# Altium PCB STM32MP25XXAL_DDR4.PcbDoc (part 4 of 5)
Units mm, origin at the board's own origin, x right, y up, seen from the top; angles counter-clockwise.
Board outline 125 x 95 mm, 6 copper layers (Top Layer, Signal Layer 1, Signal Layer 2, Signal Layer 3, Signal Layer 4, Bottom Layer), stack 1.403 mm thick; 220 components, 316 nets, 1103 pads, 939 vias.
Unrouted connection lines stored in the file: 5.
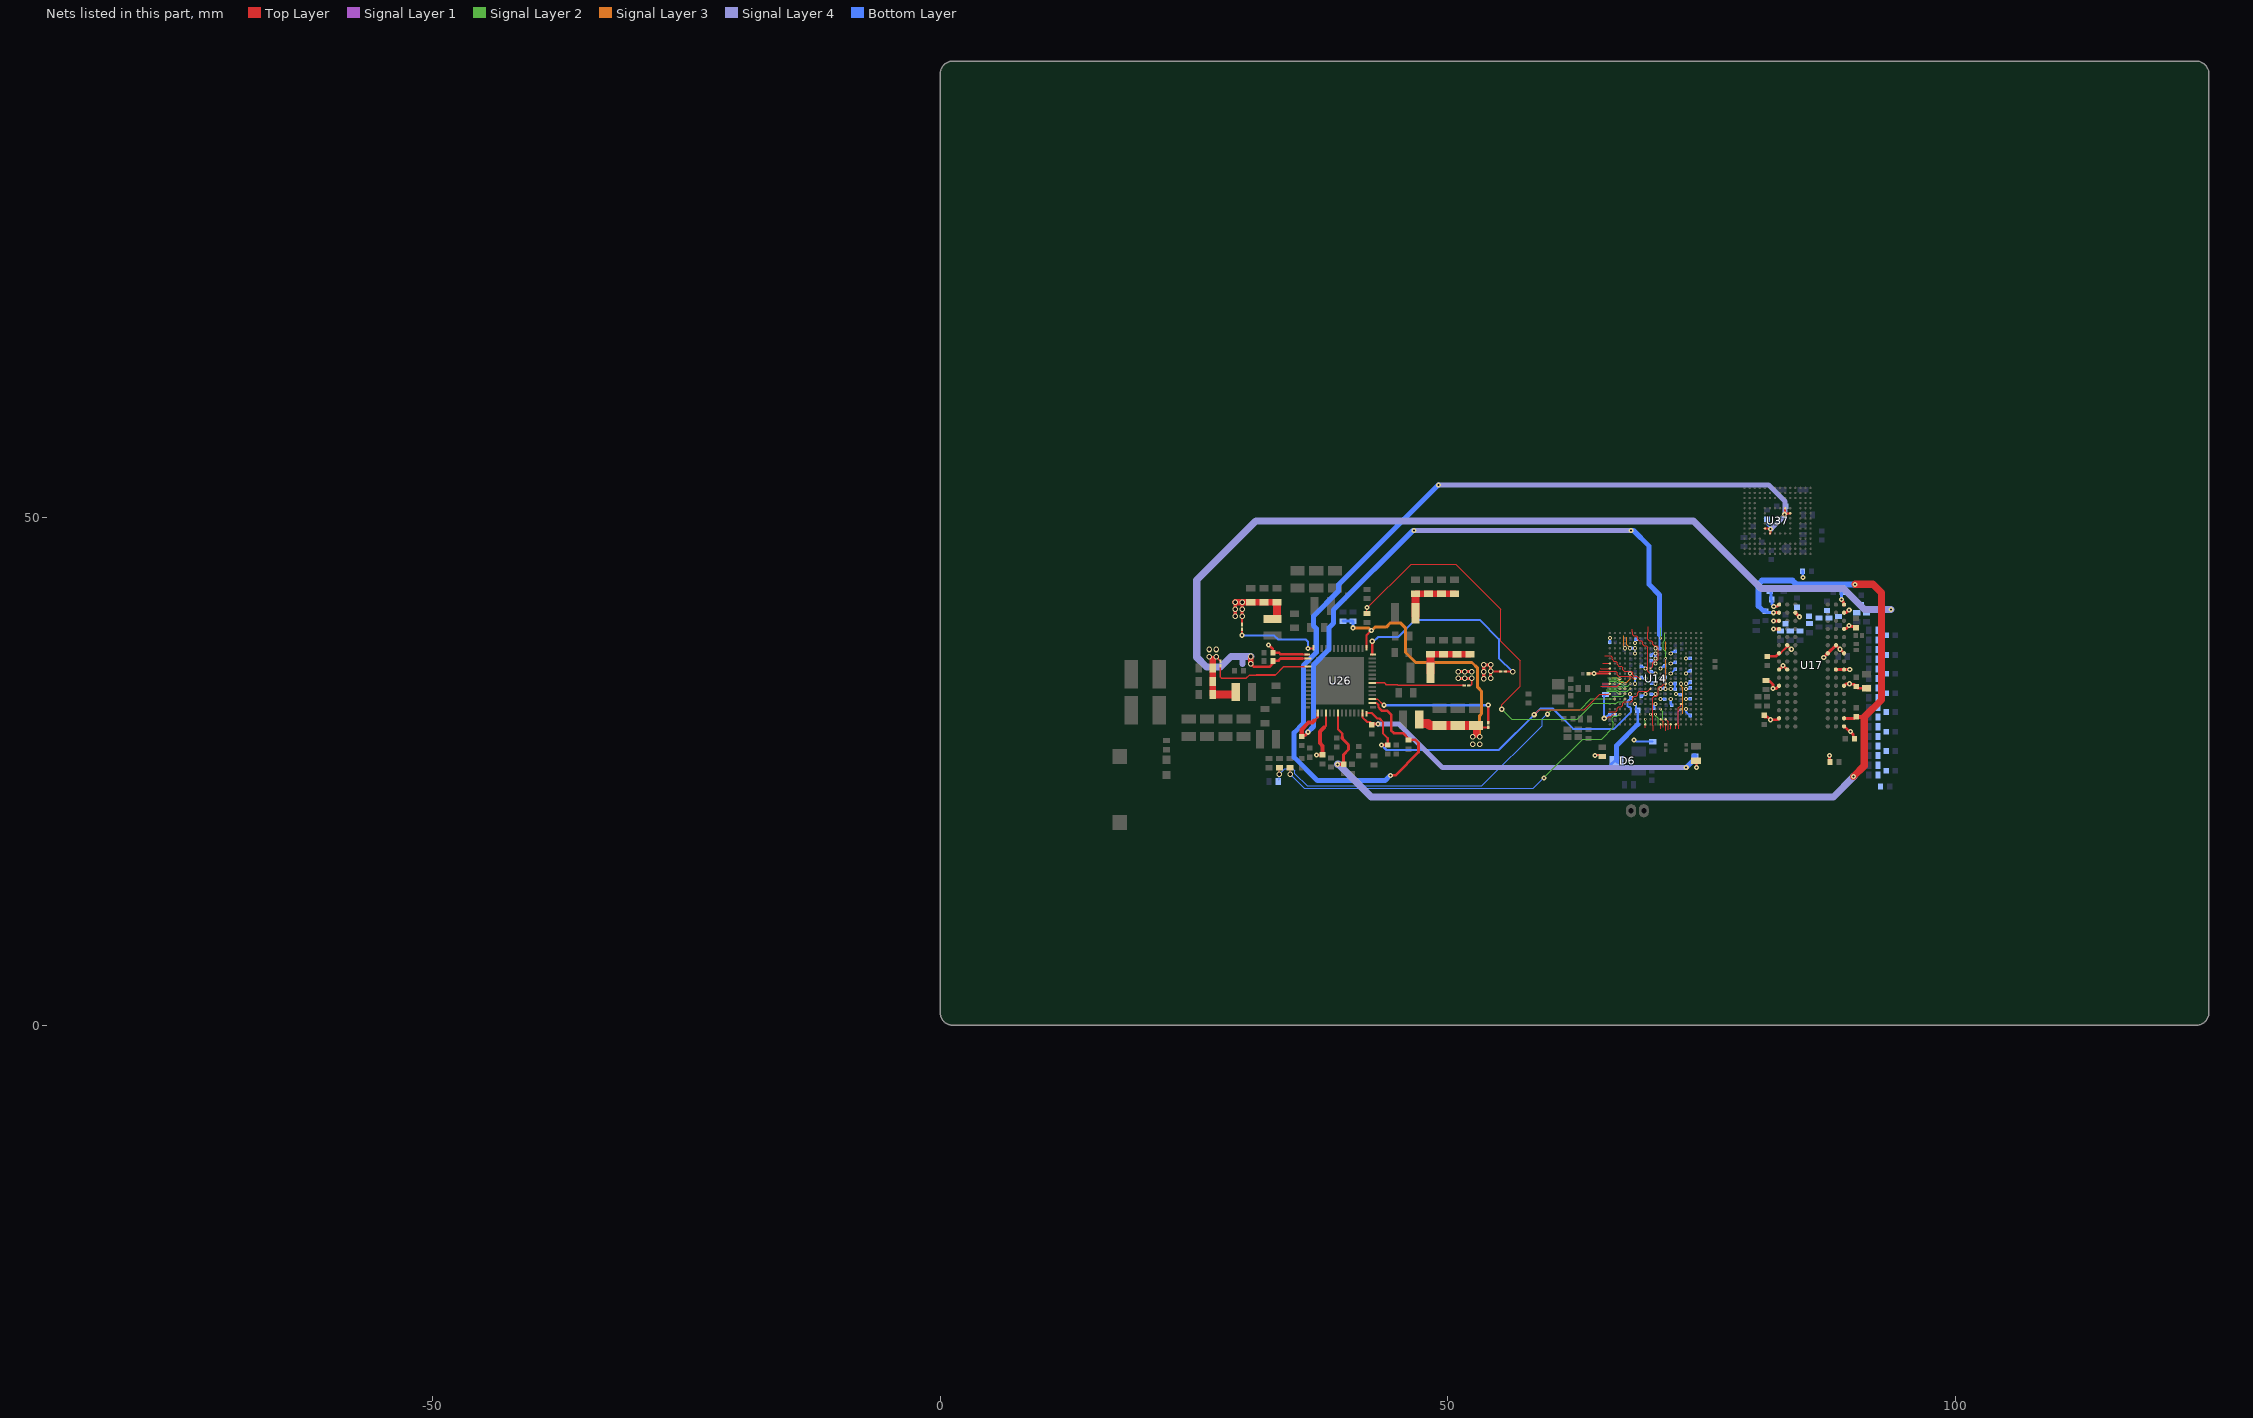
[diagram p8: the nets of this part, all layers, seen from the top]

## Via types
v1: diameter 0.5, hole 0.2, Top Layer to Bottom Layer, 292 vias
v2: diameter 0.26, hole 0.1, Top Layer to Signal Layer 1, 266 vias
v3: diameter 0.26, hole 0.1, Signal Layer 1 to Signal Layer 2, 143 vias
v4: diameter 0.4, hole 0.2, Signal Layer 1 to Signal Layer 4, 101 vias
v5: diameter 0.26, hole 0.1, Signal Layer 4 to Bottom Layer, 81 vias
v6: diameter 0.55, hole 0.35, Top Layer to Bottom Layer, 55 vias
v7: diameter 0.5, hole 0.2, Signal Layer 1 to Signal Layer 4, 1 vias

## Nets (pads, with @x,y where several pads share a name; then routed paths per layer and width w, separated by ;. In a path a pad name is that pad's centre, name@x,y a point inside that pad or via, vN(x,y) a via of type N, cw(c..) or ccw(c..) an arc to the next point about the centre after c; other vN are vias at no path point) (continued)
PH5: U14.M9 | length 5.5
  Top Layer w0.075: 65.875,30.9 66.578,30.9 66.725,31.047 66.725,31.253 66.872,31.4 67.077,31.4 67.224,31.547 67.224,31.65 ; 67.226,31.65 67.226,31.753 67.372,31.899 68.077,31.899 68.224,32.047 68.224,32.252 68.372,32.399 68.577,32.399 68.724,32.547 68.724,32.699 68.747,32.722 68.747,32.753 68.894,32.901 69.725,32.901 U14.M9@69.975,33.15
PH6: U14.L15 | length 3
  Signal Layer 3 w0.075: v4(72.975,33.65) 73.008,33.617 73.008,33.392 73.136,33.264 ; 73.137,30.714 73.137,33.264
  other v2: 72.975,33.65
PH7: U14.L12 | length 5.5
  Top Layer w0.075: 70.225,29.05 70.241,29.066 70.241,29.541 70.226,29.557 70.226,30.475 70.226,31.363 70.225,31.364 70.225,32.252 70.371,32.399 70.577,32.399 70.724,32.546 70.724,32.752 70.725,32.753 70.725,33.252 70.873,33.399 71.077,33.399 71.224,33.547 71.224,33.606 71.268,33.65 U14.L12@71.475,33.65
PH8: U14.M12 | length 4.6
  Signal Layer 3 w0.075: v4(71.475,33.15) 71.475,37.775
  other v2: 71.475,33.15
PH9: U14.W8 | length 0.3
  Top Layer w0.075: 69.475,29.325 U14.W8@69.475,29.65
PH10: U14.U10 | length 1.2
  Signal Layer 2 w0.075: v2(70.475,30.65) 70.475,30.443 70.519,30.399 70.578,30.399 70.724,30.253 70.724,29.566
  other v3: 70.475,30.65
PH11: U14.T11 | length 1.7
  Signal Layer 2 w0.075: v3(70.975,31.15) 70.975,31.1 71.2,30.875 71.2,29.518
  other v2: 70.975,31.15
PH12: U14.V8 | length 0.6
  Signal Layer 2 w0.075: 69.475,29.6 v3(69.475,30.15)
  other v2: 69.475,30.15
PH13: U14.U9 | length 1.2
  Signal Layer 2 w0.075: v3(69.975,30.65) 70.225,30.4 70.225,29.572
  other v2: 69.975,30.65
PI0: U14.H1 | length 0.9
  Top Layer w0.075: 65.05,35.175 65.075,35.15 U14.H1@65.975,35.15
PI1: U14.J9 | length 5.5
  Top Layer w0.075: 68.2,39.035 68.2,38.778 68.224,38.753 68.224,38.501 68.326,38.399 68.578,38.399 68.728,38.25 68.728,38.054 68.877,37.905 69.073,37.905 69.225,37.752 69.225,37.547 69.373,37.4 69.578,37.4 69.726,37.252 69.726,34.899 U14.J9@69.975,34.65
PI2: U14.J5 | length 2.6
  Signal Layer 3 w0.075: 66.175,34.225 66.675,34.225 67.091,33.809 67.663,33.809 67.975,34.121 v4(67.975,34.65)
  other v2: 67.975,34.65
PI3: U14.H9 | length 5.2
  Top Layer w0.075: 69.75,39.258 69.75,38.768 69.726,38.743 69.726,38.047 69.873,37.9 70.078,37.9 70.225,37.753 70.225,37.547 70.372,37.4 70.578,37.4 70.725,37.252 70.725,36.048 70.577,35.899 70.372,35.899 70.217,35.745 70.217,35.393 U14.H9@69.975,35.15
PI4: U14.G1 | length 0.7
  Top Layer w0.075: 65.325,35.625 65.35,35.65 U14.G1@65.975,35.65
PI5: U14.K7 | length 4.9
  Top Layer w0.075: 65.476,36.399 66.078,36.399 66.226,36.252 66.226,36.047 66.381,35.891 66.566,35.891 66.722,35.734 66.722,35.55 66.872,35.4 67.078,35.4 67.225,35.253 67.225,35.047 67.372,34.901 68.077,34.901 68.224,34.753 68.224,34.55 68.249,34.526 68.249,34.524 68.372,34.401 68.649,34.401 68.87,34.18 68.945,34.18 U14.K7@68.975,34.15
PI6: U14.D4 | length 1.3
  Signal Layer 3 w0.075: 67.323,38.375 67.323,37.356 67.475,37.204 v4(67.475,37.15)
  other v2: 67.475,37.15
PI7: U14.D5 | length 1.2
  Signal Layer 3 w0.075: 67.625,38.225 67.625,37.5 v4@67.975,37.15
  other v2: 67.975,37.15
  other v4: 67.975,37.15
PI8: U14.N4 | length 1.4
  Signal Layer 2 w0.075: 66.2,32.4 67.225,32.4 v3(67.475,32.65)
  other v2: 67.475,32.65
PI9: U14.K6 | length 4
  Top Layer w0.075: 64.9,34.925 64.926,34.899 66.578,34.899 66.724,34.753 66.724,34.575 66.726,34.574 66.726,34.547 66.872,34.401 68.078,34.401 68.316,34.162 68.463,34.162 U14.K6@68.475,34.15
PI10: U14.B11 | length 1
  Signal Layer 2 w0.075: v3(70.975,38.15) 70.975,39.15
  other v2: 70.975,38.15
PI11: U14.F12 | length 2.7
  Signal Layer 2 w0.075: 71.395,38.656 71.395,37.923 71.226,37.753 71.226,37.047 71.475,36.797 v3(71.475,36.15)
  other v2: 71.475,36.15
PMIC_WAKEUPn: R46.1 U14.P4 | length 42.1
  Top Layer w0.1: R46.1@42.048,40.587 42.048,41.081 46.399,45.432 50.777,45.432 55.214,40.995 55.214,37.847 57.138,35.924 57.138,33.388 55.328,31.578 v1(55.328,31.139)
  Signal Layer 2 w0.075: v1@55.325,31.15 56.325,30.15 62.775,30.15 64.34,31.715 66.616,31.715 66.801,31.899 67.225,31.899 v3(67.475,32.15)
  other v1: 42.048,41.172
  other v2: 67.475,32.15
PWR_CPU_ON: R60.1 R272.2 U14.P2 | length 39.3
  Top Layer w0.1: v6(33.398,24.739) 33.412,24.753 33.412,25.368 R60.1@33.428,25.384
  Signal Layer 2 w0.075: v1(59.825,30.65) 60.275,31.1 63.05,31.1 64.1,32.15 v2(66.475,32.15)
  Bottom Layer w0.1: R272.2@33.37,24.205 33.399,24.234 v6@33.399,24.737 ; v6(33.398,24.739) 33.959,25.3 34.725,25.3 34.95,25.075 34.95,24.8 36.166,23.584 53.344,23.584 59.297,29.537 59.297,30.197 v1@59.8,30.7
  other v3: 66.475,32.15
PWR_ON: R2.1 U14.U3 | length 37.4
  Top Layer w0.1: v6(34.473,24.739) 34.478,24.744 R2.1@34.478,25.384
  Signal Layer 2 w0.075: v1(59.475,24.375) 63.3,28.2 65.175,28.2 66.325,29.35 66.325,29.87 66.226,29.97 66.226,30.282 66.369,30.425 66.664,30.425 66.804,30.566 66.84,30.566 66.925,30.65 v3(66.975,30.65)
  Bottom Layer w0.1: v6(34.473,24.739) 35.878,23.334 58.434,23.334 v1(59.475,24.375)
  other v2: 66.975,30.65
PZ0: U14.L5 | length 2.4
  Signal Layer 2 w0.075: 65.894,33.875 66.347,33.875 66.372,33.899 66.578,33.899 66.742,33.736 66.839,33.736 66.875,33.7 67.072,33.7 67.372,33.4 67.726,33.4 v3(67.975,33.65)
  other v2: 67.975,33.65
PZ1: U14.M4 | length 1.8
  Signal Layer 2 w0.075: 65.825,33.4 67.078,33.4 67.087,33.391 67.292,33.185 67.44,33.185 v3(67.475,33.15)
  other v2: 67.475,33.15
PZ2: U14.M3 | length 1.3
  Signal Layer 2 w0.075: 65.71,33.281 65.722,33.281 65.76,33.243 66.794,33.243 66.852,33.185 66.94,33.185 v3(66.975,33.15)
  other v2: 66.975,33.15
PZ3: U14.M5 | length 2.5
  Signal Layer 2 w0.075: 65.625,33.075 66.625,33.075 66.799,32.901 67.703,32.901 67.953,33.15 v3(67.975,33.15)
  other v2: 67.975,33.15
PZ4: U14.L4 | length 1.8
  Signal Layer 2 w0.075: 65.868,34.04 66.279,34.04 66.303,34.064 66.647,34.064 66.711,34 66.772,34 66.872,33.901 67.224,33.901 v3(67.475,33.65)
  other v2: 67.475,33.65
PZ5: U14.N3 | length 1.4
  Signal Layer 2 w0.075: 65.678,32.9 66.578,32.9 66.724,32.753 66.724,32.749 66.803,32.671 66.954,32.671 v3(66.975,32.65)
  other v2: 66.975,32.65
PZ6: U14.K3 | length 1.3
  Signal Layer 2 w0.075: 65.755,34.225 66.23,34.225 66.235,34.229 66.715,34.229 66.72,34.225 66.85,34.225 66.925,34.15 v3(66.975,34.15)
  other v2: 66.975,34.15
PZ7: U14.L1 | length 0.8
  Top Layer w0.075: 65.225,33.65 U14.L1@65.975,33.65
PZ8: U14.L3 | length 2
  Top Layer w0.075: 65.083,33.4 66.725,33.4 U14.L3@66.975,33.65
PZ9: U14.L2 | length 0.5
  Signal Layer 2 w0.075: 65.95,33.65 v3(66.475,33.65)
  other v2: 66.475,33.65
UCPD1_CC1: U14.W13 | length 0.4
  Top Layer w0.075: 71.95,29.225 71.975,29.25 U14.W13@71.975,29.65
UCPD1_CC2: U14.W14 | length 0.5
  Top Layer w0.075: 72.475,29.2 U14.W14@72.475,29.65
USB3DR_DM: U14.V12 | length 1.1
  Top Layer w0.075: U14.V12@71.475,30.15 71.725,29.9 71.725,29.125
USB3DR_DP: U14.W12 | length 0.6
  Top Layer w0.075: 71.45,29.05 71.475,29.075 U14.W12@71.475,29.65
USB3DR_TXRTUNE: U14.R15 | length 2.6
  Top Layer w0.075: 72.775,29.203 72.775,29.518 72.71,29.584 72.71,30.032 72.725,30.047 72.725,31.274 72.952,31.502 72.952,31.627 U14.R15@72.975,31.65
USBH_HS_DM: U14.V11 | length 0.9
  Top Layer w0.075: U14.V11@70.975,30.15 71.225,29.9 71.225,29.375
USBH_HS_DP: U14.W11 | length 0.4
  Top Layer w0.075: 70.975,29.225 U14.W11@70.975,29.65
USBH_HS_TXRTUNE: U14.T15 | length 1.5
  Signal Layer 1 w0.075: 72.725,29.75 72.725,30.9 v2(72.975,31.15)
VBAT: C87.2 D6.3 U14.R6 | length 7.3
  Bottom Layer w0.2: v5(68.475,31.65) 68.475,31.634 68.575,31.534 C87.2@68.575,31.1 ; 68.725,29.654 C87.2@68.725,31.05
  Bottom Layer w0.3: D6.3@66.076,25.692 66.426,26.042 D6.3@66.626,26.042
  Bottom Layer w0.5: D6.3@66.825,25.975 66.626,26.174 66.626,27.555 68.725,29.654
  other v2: 68.475,31.65
  other v4: 68.475,31.65
VDD3V3_USB: C156.2 R286.1 U26.13 | length 36
  Top Layer w0.21: U26.13@41.598,30.769 41.598,30.339 42.061,29.876 42.316,29.876 42.318,29.874 42.388,29.874 42.523,29.739 C156.2@42.523,29.669
  Top Layer w0.3: C156.2@42.523,29.669 v1(43.133,29.669)
  Signal Layer 4 w0.5: v1@43.134,29.668 45.207,29.668 49.475,25.4 v1(73.5,25.4)
  Bottom Layer w0.5: v1(73.5,25.4) 74.275,26.175 74.275,26.52 74.28,26.525 R286.1@74.375,26.525
VDD_DDR: C39.2 C41.2 C70.2 C82.2 C104.2 C105.2 C106.2 C112.2 C172.2 C175.1 C178.2 C179.2 C181.2 C192.1 C200.2 C202.2 C211.1 C218.2 C284.1 C304.1 C306.1 L5.2 LNK8.2 R116.1 U14.F16 U14.J16 U14.L16 U14.M16 U14.P16 U14.T16 U17.A1 U17.A9 U17.B3 U17.B9 U17.C1 U17.D1 U17.D9 U17.F2 U17.F8 U17.G1 U17.G7 U17.G9 U17.J1 U17.J2 U17.J8 U17.J9 U17.L1 U17.L9 U17.R1 U17.T9 U26.43 | length 38.3
  Top Layer w0.15: v6(27.196,36.304) 27.598,35.902 LNK8.2@27.598,35.862
  Top Layer w0.2: U17.J1@82.65,35.05 U17.J1@82.673,35.05 ; U17.G1@82.692,36.692 82.827,36.692 83.408,37.273 83.408,37.408 U17.F2@83.45,37.45 v1(83.85,37.05) ; v1@83.05,35.427 v1(83.05,35.45)
  Top Layer w0.21: 35.673,36.539 U26.43@36.223,36.539
  Top Layer w0.25: 32.593,37.264 32.597,37.264 32.743,37.118 32.743,36.824 C39.2@32.853,36.714 ; C39.2@32.903,36.714 33.373,36.714 33.548,36.539 35.673,36.539
  Top Layer w0.28: C104.2@81.12,30.485 81.235,30.37 81.511,30.37 81.776,30.105 v1(81.785,30.105) 82.467,30.105 82.612,30.25 U17.R1@82.65,30.25 ; R116.1@81.35,33.985 81.465,33.87 81.755,33.87 82.054,33.571 82.054,33.192 v1(82.058,33.188) ; C105.2@81.46,36.355 82.355,36.355 U17.G1@82.65,36.65 ; v1@82.075,33.2 82.375,33.2 82.625,33.45 U17.L1@82.65,33.45 ; v1(82.125,41.25) 82.167,41.292 82.454,41.292 82.612,41.45 U17.A1@82.65,41.45 ; U17.G1@82.612,36.65 U17.G1@82.65,36.65 ; U17.G1@82.692,36.692 U17.G1@82.65,36.65 ; v1(83.05,35.45) U17.J2@83.45,35.05 ; v1@87.06,36.265 87.06,36.273 U17.G7@87.45,36.662 ; U17.G7@87.45,36.65 U17.F8@88.25,37.45 88.615,37.085 v1@88.625,37.085 ; C82.2@87.625,25.945 v1@87.625,26.59 ; U17.J8@88.25,35.05 U17.J9@89.05,35.05 89.057,35.043 89.607,35.043 v1(89.61,35.04) ; U17.J8@88.251,35.019 U17.J8@88.276,35.019 ; v1@88.686,37.014 U17.G9@89.05,36.65 ; v1(88.79,41.957) 88.79,41.897 89.023,41.664 89.023,41.452 U17.A9@89.05,41.425 ; U17.T9@89.05,29.45 89.085,29.45 89.527,29.008 89.638,29.008 v1(89.68,28.966) ; U17.L9@89.05,33.45 89.077,33.45 89.239,33.612 89.562,33.612 v1(89.6,33.65) ; U17.D9@89.05,39.05 89.077,39.077 89.233,39.077 89.541,39.385 89.61,39.385 89.695,39.3 90.125,39.3 C178.2@90.24,39.185 ; U17.B9@89.05,40.65 89.077,40.677 89.272,40.677 89.5,40.905 v1(89.56,40.905) ; U17.A9@89.05,41.45 U17.A9@89.05,41.454 ; v1@89.6,33.596 v1(89.6,33.65) ; v1@89.691,28.925 89.955,28.661 89.955,28.39 C106.2@90.07,28.275 ; C112.2@91.27,33.205 90.455,33.205 90.265,33.395 C181.2@90.24,33.395 90.215,33.395 90.002,33.608 89.642,33.608 v1(89.6,33.65)
  Top Layer w0.3: v1@32.342,37.515 32.593,37.264 ; v1(82.1,39.05) U17.D1@82.65,39.05 ; v1@82.1,39.85 U17.C1@82.65,39.85 ; U17.J1@82.673,35.05 v1@83.05,35.427 ; U17.B3@84.25,40.65 v1(84.65,40.25)
  Top Layer w0.64: C202.2@26.873,32.589 C41.2@26.873,33.889 C200.2@26.873,35.189 ; 26.873,35.634 26.873,36.064
  Top Layer w0.8: C202.2@27.098,32.589 L5.2@28.873,32.589
  Bottom Layer w0.2: v4(73.475,31.15) 73.475,30.875 73.75,30.6 73.825,30.6 C284.1@73.9,30.525 C284.1@73.9,30.45 ; v4(73.475,32.15) C192.1@73.925,32.15 ; v4(73.475,33.15) 73.775,33.15 C306.1@73.9,33.275 ; v4(73.475,33.65) 73.725,33.65 73.875,33.8 C211.1@73.925,33.8 ; v2(73.475,34.65) 73.675,34.85 73.85,34.85 C175.1@73.925,34.925 ; v4(73.475,36.15) C304.1@73.9,36.15
  Bottom Layer w0.28: C172.2@81.71,42.955 C172.2@81.85,42.815 ; C218.2@81.85,41.935 81.965,41.82 81.965,41.47 82.125,41.31 v1(82.125,41.25) ; C70.2@84.95,44.745 84.975,44.72 84.975,44.11 v1@85,44.085 ; v1(88.79,41.957) 88.79,42.575 C179.2@88.88,42.665
  Bottom Layer w0.3: C218.2@81.85,41.935 C172.2@81.85,42.815
  other v1: 87.62,26.595 87.05,36.25 88.65,37.05 32.348,37.487 89.55,39.385 82.09,39.85 85,44.1
  other v2: 73.475,31.15 73.475,32.15 73.475,33.15 73.475,33.65 73.475,36.15
  other v4: 73.475,34.65
  other v5: 73.475,31.15 73.475,32.15 73.475,33.15 73.475,33.65 73.475,34.65 73.475,36.15
  other v6: 26.521,36.304 26.521,37.029 27.196,37.029
VDD_DDR_FB: LNK8.1 U26.46 | length 10.2
  Top Layer w0.15: LNK8.1@27.598,35.412 27.598,34.329 27.715,34.212 30.165,34.212 30.465,34.512 31.135,34.512 31.137,34.514 33.025,34.514 33.85,35.339 U26.46@36.228,35.339
VDD_EMMC: C9.2 C117.2 C190.1 U26.16 U37.E6 U37.F5 U37.J10 U37.K9 | length 97.6
  Top Layer w0.2: U37.E6@81.25,48.95 v1@81.8,48.95 ; U37.F5@81.751,48.447 81.751,48.459 81.8,48.508 v1(81.8,48.915) ; v1(83.176,50.347) v1@83.251,50.422 ; U37.J10@83.251,50.947 83.251,50.517 83.243,50.509 83.243,50.43 v1@83.251,50.422 ; U37.K9@83.751,50.447 83.371,50.447 83.338,50.414 83.259,50.414 v1@83.251,50.422
  Top Layer w0.21: U26.16@42.568,31.739 42.998,31.739 43.186,31.551 43.186,31.326 43.332,31.18
  Top Layer w0.25: 43.33,31.177 43.496,31.011 44.026,31.011 44.423,30.614 44.423,29.064 44.698,28.789 45.593,28.789 46.148,28.234 C190.1@46.148,28.164 ; v1(44.35,24.625) 44.841,24.625 47.123,26.907 47.123,27.807 46.81,28.12 C190.1@46.164,28.12
  Signal Layer 4 w0.5: v1(49.075,53.225) 81.625,53.225 83.25,51.6 83.25,50.375 v1@83.2,50.325 ; v1(81.8,48.915) 81.888,48.915 83.176,50.203 v1(83.176,50.347)
  Bottom Layer w0.2: C9.2@81.451,49.863 81.451,49.357 v1@81.72,49.088 ; v1@83.186,50.338 83.186,51.023 C117.2@83.311,51.148
  Bottom Layer w0.5: v1(44.35,24.625) 43.825,24.1 37.182,24.1 34.875,26.407 34.875,28.825 35.775,29.725 35.775,35.445 37.054,36.724 37.054,39.096 36.775,39.375 36.775,40.309 39.252,42.786 39.252,43.402 v1(49.075,53.225)
VDD_SDCARD: C142.1 U26.4 | length 5.1
  Top Layer w0.21: 37.823,29.339 37.998,29.514 U26.4@37.998,30.769
  Top Layer w0.3: v1(37.063,26.649) C142.1@37.673,26.649
  Top Layer w0.4: C142.1@37.673,26.649 37.673,27.532 37.408,27.797 37.408,28.924 37.823,29.339
VDDA1V8_AON: C189.2 C234.2 U14.N1 U14.N5 U26.14 | length 43.6
  Top Layer w0.1: v1(58.525,30.6) 58.536,30.6 59.041,31.104 63.444,31.104 64.976,32.636 65.323,32.636 65.961,32.636 U14.N1@65.975,32.65
  Top Layer w0.21: U26.14@41.998,30.769 42.508,30.769 43.046,30.231 43.286,30.231 43.643,29.873 43.643,28.741 44.098,28.286 C189.2@44.098,27.629
  Top Layer w0.3: v1(43.488,27.629) C189.2@44.098,27.629
  Bottom Layer w0.2: v1@43.469,27.63 43.974,27.126 55.051,27.126 v1(58.525,30.6) 59.125,31.2 60.375,31.2 62.364,29.211 66.397,29.211 68.07,30.884 68.07,31.221 67.953,31.338 67.82,31.338 67.713,31.445 67.713,31.945 67.82,32.052 67.878,32.052 67.995,32.169 C234.2@68.07,32.245 ; v4(67.975,32.65) 67.975,32.35 67.995,32.33 67.995,32.32 C234.2@68.065,32.25
  other v2: 67.975,32.65
  other v5: 67.975,32.65
VDDCORE: C16.2 C22.2 C23.2 C24.2 C183.2 C195.1 C196.2 C201.2 C203.1 C213.2 C215.2 C289.2 C299.2 C300.2 L2.2 LNK2.2 R11.1 U14.B1 U14.C6 U14.G10 U14.H11 U14.J1 U14.J10 U14.K11 U14.L10 U14.N8 U14.N10 | length 17
  Top Layer w0.2: C22.2@50.673,42.514 C22.2@50.721,42.562 ; 54.598,34.839 LNK2.2@55.214,34.839 ; C201.2@63.9,34.65 v1(64.425,34.65) ; v1@64.425,34.625 64.45,34.65 U14.J1@65.975,34.65 ; R11.1@74.475,26.075 74.525,26.025 v1(74.525,25.4) v1@74.525,25.375
  Top Layer w0.3: v6(53.554,34.163) v6(53.554,34.838) v6(53.554,35.513) 54.229,35.513 v6@54.229,34.163
  Top Layer w0.64: C183.2@46.848,42.514 C24.2@48.123,42.514 C23.2@49.398,42.514 C22.2@50.673,42.514
  Top Layer w0.8: L2.2@46.813,40.339 L2.2@46.813,40.589 C183.2@46.813,42.312
  Bottom Layer w0.2: C215.2@65.975,37.75 v4(65.975,38.15) ; v4(68.475,37.65) 68.475,37.98 C16.2@68.55,38.055 ; C300.2@69.05,32.425 69.125,32.5 69.309,32.5 69.459,32.65 v2(69.475,32.65) ; C195.1@70.05,32.625 70.434,32.625 70.459,32.65 v2(70.474,32.649) ; C289.2@70.05,33.725 70.083,33.692 70.417,33.692 70.459,33.65 v2(70.475,33.65) ; C196.2@70.05,34.825 70.125,34.75 70.359,34.75 70.459,34.65 v2(70.475,34.65) ; C213.2@70.05,35.925 70.125,35.85 70.275,35.85 v2(70.475,35.65) ; v2(70.975,34.15) 70.991,34.15 71.073,34.232 71.327,34.232 C203.1@71.4,34.305 ; v2(70.975,35.15) 70.991,35.15 71.171,35.33 71.325,35.33 C299.2@71.4,35.405
  other v2: 68.475,37.65 65.975,38.15
  other v4: 69.475,32.65 70.474,32.649 70.475,33.65 70.975,34.15 70.475,34.65 70.975,35.15 70.475,35.65
  other v5: 69.475,32.65 70.474,32.649 70.475,33.65 70.975,34.15 70.475,34.65 70.975,35.15 70.475,35.65 68.475,37.65 65.975,38.15
  other v6: 54.224,34.193 54.224,34.868 54.224,35.543
VDDCORE_FB: LNK2.1 U26.28 | length 20.6
  Top Layer w0.2: U26.28@42.568,36.539 v1(42.568,37.839) ; LNK2.1@55.664,34.839 v6@56.274,34.839
  Bottom Layer w0.2: v1@42.544,37.837 42.601,37.894 42.775,37.894 43.128,38.248 45.108,38.248 46.801,39.941 53.147,39.941 55.049,38.039 55.049,36.178 v6@56.407,34.82 ; v1@42.549,37.84 42.606,37.898 42.78,37.898 43.133,38.251
  other v6: 56.431,34.822
VDDCPU: C26.2 C27.2 C28.2 C177.1 C191.1 C194.2 C283.2 C287.2 L3.2 LNK4.1 U14.E13 U14.G13 U14.J13 U14.L13 U14.M13 | length 13.3
  Top Layer w0.2: LNK4.1@29.748,39.489 v6(29.748,40.312)
  Top Layer w0.3: v6(29.073,40.312) v6(29.073,40.987) v6(29.073,41.662) v6(29.748,41.662) v6(29.748,40.987) v6(29.748,40.312)
  Top Layer w0.64: v6(29.073,41.662) 29.073,41.664 C27.2@30.598,41.664 C28.2@31.898,41.664 C26.2@33.198,41.664
  Top Layer w0.8: L3.2@32.748,40.014 33.198,40.014 33.198,41.312
  Bottom Layer w0.2: v2(71.975,33.65) C194.2@72.4,33.65 ; v2(71.975,34.65) C177.1@72.4,35.075 ; v2(71.975,35.65) 71.991,35.65 72.058,35.717 72.367,35.717 C191.1@72.45,35.8 ; v2(71.975,36.65) 72.125,36.8 72.4,36.8 C287.2@72.475,36.875 ; v5@72,33.125 C283.2@72.4,33.125 ; C283.2@72.375,33.1 C283.2@72.4,33.125 ; C194.2@72.4,33.675 C194.2@72.4,33.65 ; C177.1@72.4,35.1 C177.1@72.425,35.1 ; C194.2@72.425,33.65 C194.2@72.4,33.65 ; C283.2@72.4,33.125 C194.2@72.4,33.65
  other v2: 71.975,33.15
  other v4: 71.975,33.15 71.975,33.65 71.975,34.65 71.975,35.65 71.975,36.65
  other v5: 71.975,33.15 71.975,33.65 71.975,34.65 71.975,35.65 71.975,36.65
VDDCPU_FB: LNK4.2 U26.42 | length 8.6
  Top Layer w0.2: v1(29.748,38.429) LNK4.2@29.748,39.039 ; v1(36.223,37.114) U26.42@36.793,37.114
  Bottom Layer w0.2: v1(29.748,38.429) 32.878,38.427 33.293,38.012 36.022,38.012 36.224,37.81 v1@36.224,37.112
VDDGPU: C1.2 C2.2 C3.2 C4.2 C5.2 C34.2 C35.2 C36.2 C37.2 L4.2 LNK7.2 U14.M11 U14.N14 U14.P11 U14.P13 U14.R10 | length 11.6
  Top Layer w0.15: LNK7.2@52.073,33.489 52.08,33.497 52.283,33.497 52.371,33.584 v6(52.371,34.177)
  Top Layer w0.2: C35.2@52.448,36.531 C35.2@52.496,36.484
  Top Layer w0.3: v6(51.021,34.177) v6(51.696,34.177) v6(52.371,34.177) ; v6(51.021,34.852) v6(51.696,34.852) v6(52.371,34.852)
  Top Layer w0.64: C37.2@48.298,36.539 C36.2@49.598,36.539 C34.2@50.898,36.539 C35.2@52.198,36.539
  Top Layer w0.8: L4.2@48.323,34.739 48.323,36.212
  Bottom Layer w0.2: C2.2@70.25,31.225 70.315,31.29 70.315,31.491 v2(70.474,31.65) ; v5(70.975,32.15) 71.355,32.15 C1.2@71.4,32.105 ; v2(70.975,33.149) 70.991,33.149 71.023,33.181 71.376,33.181 C3.2@71.4,33.205 ; v2(71.975,32.15) 71.975,31.675 C4.2@72.075,31.575 ; v2(72.475,32.65) 72.825,32.65 C5.2@72.9,32.575
  other v2: 70.975,32.15
  other v4: 70.474,31.65 70.975,32.15 71.975,32.15 72.475,32.65 70.975,33.149
  other v5: 70.474,31.65 71.975,32.15 72.475,32.65 70.975,33.149
VDDGPU_FB: LNK7.1 U26.21 | length 9.3
  Top Layer w0.15: U26.21@42.448,33.739 43.781,33.739 43.958,33.562 45.038,33.562 45.111,33.489 LNK7.1@51.623,33.489
VDDIO: C17.2 C19.2 C186.2 C187.2 C197.2 C205.2 C219.2 C307.1 L6.2 LNK11.2 R27.2 R67.2 R260.2 R261.2 U14.D6 U14.E6 U14.E10 U14.F10 U14.H8 U14.K8 U14.L6 U26.29 | length 40.2
  Top Layer w0.2: U26.29@41.998,37.184 41.998,38.437 v1(42.473,38.912) ; C186.2@52.798,29.539 52.983,29.354 LNK11.2@53.998,29.354 ; v1(64.525,26.6) 64.538,26.613 65.213,26.613 R27.2@65.225,26.625
  Top Layer w0.64: 52.798,28.664 C186.2@52.798,29.094
  Top Layer w0.9: L6.2@47.248,29.739 48.048,29.739 48.248,29.539 C187.2@49.198,29.539 C19.2@50.998,29.539 C186.2@52.798,29.539
  Signal Layer 3 w0.3: v1@40.683,39.165 42.198,39.165 42.449,38.914 v1@42.474,38.914 ; v1@42.474,38.911 42.528,38.911 42.839,39.222 43.942,39.222 44.372,39.651 45.33,39.651 45.854,39.127 45.854,36.739 46.855,35.738 52.398,35.738 52.95,35.186 52.95,33.294 53.35,32.894 53.35,30.711 53.151,30.513 v6(53.15,28.424)
  Bottom Layer w0.1: v4(68.475,36.65) v4(68.475,37.15)
  Bottom Layer w0.2: C17.2@68.045,37.15 v4(68.475,37.15) ; v5(68.341,28.116) 68.383,28.116 68.558,27.941 R67.2@70.199,27.941 ; v2(68.475,33.65) 68.475,34.2 C197.2@68.55,34.275 ; C197.2@68.5,34.275 68.525,34.25 C197.2@68.575,34.2 ; C205.2@69.025,35.375 69.1,35.3 69.325,35.3 v2(69.475,35.15) ; C307.1@69.05,34.275 69.175,34.15 v2(69.475,34.15) ; C219.2@70.05,36.475 70.214,36.639 v5@70.464,36.639 ; v5(70.474,36.149) 70.463,36.16 70.463,36.203 70.45,36.215 70.45,36.583 70.464,36.596 v5@70.464,36.639 ; v4(70.475,36.65) v5@70.464,36.639
  Bottom Layer w0.3: R260.2@39.709,39.82 40.684,39.82 40.673,39.81 40.673,39.178 v1@40.663,39.168
  other v1: 40.682,39.166
  other v2: 70.474,36.149 68.475,36.65 70.475,36.65 68.475,37.15
  other v4: 68.475,33.65 69.475,34.15 69.475,35.15 70.474,36.149
  other v5: 68.475,33.65 69.475,34.15 69.475,35.15 68.475,36.65 70.475,36.65 68.475,37.15
  other v6: 52.475,27.699 53.15,27.699 52.475,28.424
  other v7: 68.35,28.125
VDDIO_FB: LNK11.1 U26.17 | length 13.4
  Top Layer w0.15: U26.17@42.568,32.139 43.098,32.139 43.701,31.536 v1(43.713,31.536)
  Top Layer w0.2: LNK11.1@53.998,29.804 v1(53.998,31.539)
  Bottom Layer w0.15: v1@53.996,31.534 v1@53.999,31.537
  Bottom Layer w0.2: v1(43.713,31.536) v1@53.996,31.534
VDDIO_SDCARD: C210.2 C217.1 U14.D10 U26.2 | length 63
  Top Layer w0.21: 36.857,30.012 37.198,30.353 U26.2@37.198,30.769
  Top Layer w0.3: C217.1@35.623,28.519 35.668,28.564 35.957,28.564 36.233,28.84 v1(36.233,28.876)
  Top Layer w0.4: C217.1@35.623,28.459 35.623,28.519 35.623,29.154 36.297,29.829 36.673,29.829 36.857,30.012
  Signal Layer 4 w0.5: v1(46.7,48.75) 46.707,48.757 68.068,48.757 v1(68.075,48.75)
  Bottom Layer w0.2: v5(70.475,37.15) 70.875,37.15 C210.2@70.9,37.125 ; C210.2@70.875,37.096 70.875,38.475
  Bottom Layer w0.5: v1@36.214,28.877 36.775,29.438 36.775,35.501 38.318,37.044 38.318,39.173 38.761,39.616 38.761,40.93 46.581,48.75 v1(46.7,48.75) ; v1(68.075,48.75) 68.3,48.75 69.85,47.2 69.85,43.425 70.875,42.4 70.875,38.475
  other v2: 70.475,37.15
  other v4: 70.475,37.15
VPP_DDR: C91.1 C252.2 C255.2 U17.B1 U17.R9 U26.7 | length 97.5
  Top Layer w0.21: U26.7@39.198,30.769 39.198,29.164 39.613,28.749 39.613,28.392
  Top Layer w0.3: v1(39.138,25.719) C91.1@39.748,25.719 ; 39.613,28.392 39.613,28.257 40.233,27.637 40.233,27.174 39.748,26.689 C91.1@39.748,25.869 ; v1(82.09,40.65) U17.B1@82.65,40.65 ; U17.R9@89.05,30.25 C252.2@90.07,30.25
  Top Layer w0.4: C252.2@90.24,30.395 91.04,30.395
  Top Layer w0.7: v1@89.994,24.519 91.04,25.565 91.04,30.395 ; v1(90.125,43.45) 91.89,43.45 92.725,42.615 92.725,32.055 91.09,30.42
  Signal Layer 4 w0.7: v1(39.138,25.719) 39.259,25.719 42.471,22.507 88.009,22.507 v1@90.008,24.505
  Bottom Layer w0.3: C255.2@81.254,40.851 81.455,40.65 v1(82.09,40.65)
  Bottom Layer w0.44: 80.604,41.321 81.095,40.83 81.275,40.83 C255.2@81.31,40.795
  Bottom Layer w0.6: 80.604,41.321 80.604,43.446 80.983,43.825 83.95,43.825 84.33,43.445 v1@90.125,43.445 ; v1(90.125,43.45) v1@90.126,43.451
  other v1: 90,24.525
VREF+: C248.2 C250.2 R269.2 U14.U2 | length 4.9
  Top Layer w0.075: v1@65.375,30.3 65.793,30.3 65.878,30.384 66.062,30.384 66.224,30.547 66.224,30.574 66.3,30.65 U14.U2@66.475,30.65
  Bottom Layer w0.2: v1@65.4,30.325 65.4,32.45 R269.2@65.55,32.6 ; v1(65.425,30.25) 65.506,30.25 65.781,30.525 65.875,30.525 C248.2@65.95,30.6 ; C248.2@65.955,30.605 65.96,30.6 66.565,30.6 C250.2@66.57,30.605
VTT_DDR: C40.2 C144.2 C145.2 C146.2 C160.2 C226.2 C239.2 C254.2 C256.2 C257.2 C258.2 C259.2 C261.2 C265.2 C266.2 R252.2 R253.2 R254.2 R255.2 R256.2 R257.2 R258.2 R259.2 R263.2 R264.2 R265.2 R266.2 R268.2 R271.2 R273.2 R275.2 R276.2 R277.2 R278.2 R279.2 R280.2 R281.2 R282.2 R283.2 R284.2 U26.44 | length 95.8
  Top Layer w0.21: 35.673,36.139 U26.44@36.228,36.139
  Top Layer w0.25: v6(30.6,35.612) 30.873,35.339 32.473,35.339 32.718,35.584 32.718,35.774 32.833,35.889 C40.2@32.903,35.889 ; C40.2@32.908,35.774 33.063,35.929 33.338,35.929 33.548,36.139 35.673,36.139
  Top Layer w0.5: v6(30.6,35.612) v6@30.6,36.335
  Signal Layer 4 w0.6: 29.774,35.613 29.774,36.336
  Signal Layer 4 w0.7: v6@30.599,36.336 29.774,36.336 28.643,36.336 27.608,35.301 26.236,35.301 25.282,36.255 25.282,43.871 31.098,49.687 74.213,49.687 80.859,43.041 88.986,43.041 91.051,40.976 v1@93.674,40.976
  other v1: 93.675,40.975
  other v6: 30.598,36.337
pads on no net: U14.G17 U14.K17 U14.N17 U14.P1 U14.P17 U14.T12 U17.P9 U17.T7 U37.A1 U37.A2 U37.A7 U37.A8 U37.A9 U37.A10 U37.A11 U37.A12 U37.A13 U37.A14 U37.B1 U37.B7 U37.B8 U37.B9 U37.B10 U37.B11 U37.B12 U37.B13 U37.B14 U37.C1 U37.C3 U37.C5 U37.C7 U37.C8 U37.C9 U37.C10 U37.C11 U37.C12 U37.C13 U37.C14 U37.D1 U37.D2 U37.D3 U37.D4 U37.D12 U37.D13 U37.D14 U37.E1 U37.E2 U37.E3 U37.E5 U37.E8 U37.E9 U37.E10 U37.E12 U37.E13 U37.E14 U37.F1 U37.F2 U37.F3 U37.F10 U37.F12 U37.F13 U37.F14 U37.G1 U37.G2 U37.G3 U37.G10 U37.G12 U37.G13 U37.G14 U37.H1 U37.H2 U37.H3 U37.H12 U37.H13 U37.H14 U37.J1 U37.J2 U37.J3 U37.J12 U37.J13 U37.J14 U37.K1 U37.K2 U37.K3 U37.K6 U37.K7 U37.K10 U37.K12 U37.K13 U37.K14 U37.L1 U37.L2 U37.L3 U37.L12 U37.L13 U37.L14 U37.M1 U37.M2 U37.M3 U37.M7 U37.M8 U37.M9 U37.M10 U37.M11 U37.M12 U37.M13 U37.M14 U37.N1 U37.N3 U37.N6 U37.N7 U37.N8 U37.N9 U37.N10 U37.N11 U37.N12 U37.N13 U37.N14 U37.P1 U37.P2 U37.P7 U37.P8 U37.P9 U37.P10 U37.P11 U37.P12 U37.P13 U37.P14
copper on no net: | length 0.4
  Signal Layer 1 w0.1: 73.712,22.092 73.715,22.095
  Signal Layer 2 w0.075: 69.22,45.77 69.225,45.775
  Signal Layer 4 w0.09: 54.67,69.65 54.673,69.647 ; 54.673,69.127 54.75,69.05
  Bottom Layer w0.09: 29.625,93.625 29.8,93.8

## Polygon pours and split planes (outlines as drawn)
5V_STLK on Signal Layer 4 "5V_STLK" (solid, pour order 297): 125,95.201 125,0.3 0,0.3 0,95.201
VDDGPU on Signal Layer 4 "VDDGPU" (solid, remove dead copper, pour order 272): 53.029,33.196 55.325,30.9 70.275,30.9 70.275,32.1 70.725,32.1 70.725,33.35 73.25,33.35 73.25,28.075 49.673,28.075 46.8,30.879 46.8,34.699 47.529,35.428 53.029,35.428
VDDCPU on Signal Layer 4 "VDDCPU" (solid, remove dead copper, pour order 292): 46.237,38.475 69.4,38.475 71.025,36.85 71.025,32.9 73.2,32.9 73.2,42.193 72.754,42.638 40.002,42.638 40.002,42.651 39.116,43.538 30.242,43.538 28.618,41.913 28.618,39.888 28.718,39.988 38.515,39.988 39.454,39.05 39.542,39.138 45.574,39.138
3V3 on Signal Layer 4 "3V3_L4" (solid, remove dead copper, pour order 294): 33.955,30.677 32.353,29.075 15.11,29.075 15.11,19.532 37.399,19.532 37.399,30.677
VDD_DDR on Signal Layer 4 "VDD_DDR" (solid, remove dead copper, pour order 293): 28.618,39.875 32.3,39.875 32.625,39.55 32.625,37.225 32.008,36.608 28.617,36.609 27.615,35.606 26.317,35.606 25.645,36.278 25.645,43.516 30.252,48.123 75.839,48.123 81.412,42.55 91.14,42.55 91.14,26.204 79.052,26.122 76.174,29 73.2,31.975 73.2,42.125 73.234,42.159 73.159,42.233 28.938,42.233 28.618,41.913
VDDCORE on Signal Layer 4 "VDDCORE" (solid, remove dead copper, pour order 291): 53.144,33.175 55.394,30.925 70.975,30.925 70.975,36.735 69.335,38.375 53.144,38.375
GND on Bottom Layer "GND" (solid, remove dead copper, pour order 257): 0,95 125,95 125,0 0,0
VTT_DDR on Bottom Layer "VTT_DDR_L06_P247" (solid, remove dead copper, pour order 247): 90.467,41.805 90.467,44.095 95.217,44.095 95.217,41.095 93.477,39.345 93.477,23.345 92.143,23.345 92.143,24.338 92.143,39.989 91.857,40.275 88.893,40.275 87.653,39.035 85.697,39.035 85.467,38.805 82.537,38.805 82.537,39.785 83.197,39.785 84.092,40.68 84.092,41.22 84.217,41.345 85.017,41.345 85.217,41.145 85.217,40.885 87.157,40.885 87.157,41.805
GND on Top Layer "GND_L01_P283" (solid, pour order 283): -0.345,95.136 125,95.136 125,-0.164 0.005,-0.164
VDDIO on Top Layer "VDDIO" (solid, pour order 280): 41.893,36.909 41.893,38.707 42.428,39.242 42.61,39.242 43.048,38.803 43.048,38.262 42.348,37.562 42.348,36.909
VDDCORE on Top Layer "VDDCORE_TOP" (solid, pour order 278): 51.905,42.834 54.787,39.952 54.787,33.725 54.792,33.72 53.338,33.72 52.793,34.265 52.793,38.966 52.42,39.339 50.773,39.339 46.413,39.339 46.403,42.834
NetL6_1 on Top Layer "NetL13_1" (solid, pour order 282): 44.273,32.002 44.736,31.539 45.998,31.539 45.998,29.239 45.996,29.237 44.699,29.237 44.699,30.861 44.273,31.287
3V3 on Top Layer "3V3" (solid, pour order 281): 23.785,26.687 23.96,26.512 30.308,26.512 31.61,27.814 31.61,28.662 23.986,28.662 23.785,28.462
VDDGPU on Top Layer "VDDGPU_TOP" (solid, pour order 279): 52.501,33.739 52.643,33.881 52.643,36.859 47.923,36.859 47.923,33.739
VDDCPU on Top Layer "VDDCPU_TOP" (solid, pour order 277): 28.71,41.984 28.71,40.137 29.233,39.614 33.648,39.614 33.643,39.619 33.643,41.984
5V_STLK on Top Layer "5V_VIN" (solid, pour order 259): 33.408,33.759 34.065,33.759 34.248,33.942 34.248,33.602 33.765,33.119 33.408,33.119
GND on Signal Layer 3 "GND" (solid, pour order 298): 125,95 125,0 0,0 0,95
VDDIO on Signal Layer 3 "VDDIO" (solid, remove dead copper, pour order 252): 69.775,35.95 70.025,36.2 70.025,36.9 70.8,36.9 70.8,33.9 70.525,33.9 70.525,26.35 53.129,26.35 51.952,27.527 51.952,29.784 53.344,31.176 63.125,31.176 63.125,34.2 68.275,34.2 68.275,34.3 69.275,34.3 69.275,35.95
1V8 on Signal Layer 3 "1V8_L04_P295" (solid, pour order 295): 66.275,34.3 71.55,34.3 71.55,27.275 73.9,27.275 86.65,27.275 86.65,52.875 76.525,52.875 76.525,49.35 39.4,49.35 39.4,39.55 66.275,39.55
GND on Signal Layer 2 "GND_L03_P299" (solid, pour order 299): -0.037,95 125,95 125,0 0.311,0
VDDIO on Signal Layer 2 "VDDIO_L03_P258" (solid, pour order 258): 70.675,37.35 67.95,37.35 67.95,33.35 70.675,33.35
GND on Signal Layer 1 "gnd" (solid, pour order 236): -0.171,95 125,95 125,0 0.002,0

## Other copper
Top Layer:
  rectangle net VDD_DDR: 26.553,31.939 29.523,33.739
  region net GND: 35.798,37.824 35.705,37.824 ccw(c35.705,37.723) 35.633,37.794 35.353,37.514 ccw(c35.425,37.442) 35.323,37.442 35.323,37.114 35.823,37.114 cw(c36.221,37.121) 36.213,37.519 36.473,37.514 ccw(c36.473,37.562) 36.507,37.528 36.603,37.624
  region net 5V_STLK: 36.128,38.663 36.029,38.564 35.673,38.564 cw(c35.673,38.914) 35.323,38.914 35.323,38.964 34.598,38.964 ccw(c34.598,38.889) 34.523,38.889 34.523,38.539 ccw(c34.725,38.536) 34.723,38.334 37.348,38.334 37.748,37.939 38.01,37.939 37.289,38.66 37.023,38.664
  region net 5V_STLK: 44.503,37.919 44.328,37.811 ccw(c44.461,37.612) 44.292,37.781 44.251,37.74 ccw(c44.511,37.481) 44.144,37.481 44.144,37.465 ccw(c44.499,37.465) 44.248,37.214 44.248,35.678 44.247,35.677 44.245,35.69 43.774,35.219 43.168,35.219 43.168,35.484 43.404,35.484 43.878,35.958 43.878,38.486 44.206,38.809 45.223,38.809 45.223,37.919
  pour cut-out: 78.901,53.292 86.176,53.292 86.176,46.09 78.901,46.09
  region net 5V_STLK: 45.023,37.489 45.173,37.339 45.173,37.089 44.373,37.089 44.373,37.339 44.523,37.489 44.523,37.739 45.023,37.739
  pour cut-out: 46.753,31.014 48.528,31.014 48.528,29.739 47.198,29.739
  pour cut-out: 29.393,31.789 30.453,31.789 30.453,33.889 29.393,33.889
  region net 5V_STLK: 33.773,31.039 33.614,31.039 33.587,31.013 33.546,30.981 33.5,30.954 33.452,30.934 33.401,30.921 33.349,30.914 33.323,30.913 32.823,30.913 32.797,30.914 32.745,30.921 32.694,30.934 32.646,30.954 32.6,30.981 32.559,31.013 32.548,30.589 32.548,30.084 32.273,30.084 32.273,29.444 32.728,29.444 33.497,30.213 33.497,30.323 33.501,30.366 33.511,30.409 33.527,30.449 33.55,30.485 33.578,30.518 33.936,30.876
  pour cut-out: 32.398,30.739 30.448,30.739 30.448,30.164 32.398,30.164
  pour cut-out: 31.698,39.744 31.698,38.684 33.798,38.684 33.798,39.744
  pour cut-out: 38.053,42.364 37.333,42.364 37.333,40.264 38.053,40.264
  pour cut-out: 32.838,29.239 31.778,29.239 31.778,27.139 32.838,27.139
  pour cut-out: 46.343,41.389 45.283,41.389 45.283,39.289 46.343,39.289
  pour cut-out: 47.853,35.589 46.793,35.589 46.793,33.489 47.853,33.489
  pour cut-out: 46.798,31.214 45.998,31.214 45.998,29.114 46.798,29.114
  region net GND: 36.473,37.514 36.138,37.514 36.138,37.524
  region net 5V_STLK: 38.323,37.864 38.298,37.864 37.528,38.634 37.528,38.964 38.168,38.964 38.168,38.744 38.298,38.614 38.298,38.064
  region net GND: 42.819,36.795 42.918,36.795 42.947,36.792 42.976,36.783 43.002,36.769 43.025,36.751 43.043,36.728 43.068,36.694 43.068,36.369 43.168,36.369 43.168,37.069 42.819,37.069
  region net 5V_STLK: 34.148,39.439 34.193,39.484 34.548,39.484 34.548,38.789 34.298,38.789 34.148,38.939 33.898,38.939 33.898,39.439
  region net 5V_STLK: 45.073,39.139 45.223,38.989 45.223,38.739 44.423,38.739 44.423,38.989 44.573,39.139 44.573,39.389 45.073,39.389
  pour cut-out: 23.798,28.912 30.448,28.912 30.448,29.712 23.798,29.712
  pour cut-out: 53.498,30.064 48.528,30.064 48.528,30.714 53.498,30.714
  region net 5V_STLK: 45.093,36.314 45.093,35.459 45.023,35.389 44.898,35.514 44.298,35.514 44.453,35.669 44.453,36.314
  region net 5V_STLK: 44.973,31.989 44.875,32.087 44.875,32.764 45.518,32.764 45.518,32.034 45.473,31.989 45.473,31.739 44.973,31.739
  region net GND: 43.728,34.264 44.178,34.264 44.178,33.964 44.053,33.839 43.878,34.014 43.728,34.014
  region net 5V_STLK: 45.023,35.389 44.448,34.814 43.773,34.814 43.773,34.989 44.298,35.514
  region net NetL5_1: 30.323,34.087 30.548,34.312 31.923,34.312 31.923,32.462 31.4,31.939 31.123,31.939 30.323,31.939
  region net NetL1_1: 38.893,40.414 38.548,40.069 38.093,40.524 38.093,42.214 38.893,42.214
  region net NetL7_1: 33.773,28.489 33.473,28.189 32.698,28.189 32.698,29.089 33.773,30.159
  region net NetL3_1: 34.681,38.184 34.652,38.187 34.623,38.196 34.549,38.228 34.523,38.242 34.501,38.261 34.445,38.319 34.426,38.342 34.412,38.368 34.386,38.433 34.379,38.455 34.356,38.486 34.331,38.506 34.295,38.53 34.249,38.539 33.473,38.539 33.473,37.402
  region net NetL3_1: 33.473,37.114 32.286,38.301 33.386,38.301 33.473,38.214 37.078,38.214 37.318,37.974 35.688,37.974 35.666,37.972 35.646,37.968 35.618,37.959 35.599,37.952 35.573,37.938 35.556,37.927 35.533,37.908 35.239,37.613 35.22,37.591 35.209,37.574 35.2,37.558 35.188,37.529 35.184,37.517 35.179,37.501 35.175,37.481 35.174,37.466 35.172,37.452 35.172,37.114
  region net NetL4_1: 45.423,35.739 45.423,33.739 46.332,33.739 46.332,35.739
  region net NetL2_1: 44.548,40.364 44.548,39.589 44.413,39.589 43.723,38.899 43.723,36.139 43.248,35.664 42.923,35.664 42.923,35.814 43.012,35.814 43.168,35.97 43.348,36.15 43.403,36.233 43.423,36.33 43.423,36.881 43.468,36.989 43.468,37.149 43.407,37.296 43.295,37.408 43.168,37.461 43.148,37.464 43.148,41.241 43.496,41.589 44.413,41.589 44.548,41.454 44.548,41.339
  region net GND: 38.923,45.564 39.073,45.414 39.073,45.164 38.198,45.164 38.198,45.589 38.423,45.814 38.923,45.814
  region net GND: 38.923,45.564 38.773,45.414 38.773,45.164 39.598,45.164 39.598,45.639 39.423,45.814 38.923,45.814
  region net GND: 37.073,45.564 37.223,45.414 37.223,45.164 36.348,45.164 36.348,45.589 36.573,45.814 37.073,45.814
  region net GND: 37.073,45.564 36.923,45.414 36.923,45.164 37.748,45.164 37.748,45.639 37.573,45.814 37.073,45.814
  region net GND: 35.223,45.564 35.073,45.414 35.073,45.164 35.898,45.164 35.898,45.639 35.723,45.814 35.223,45.814
  region net GND: 35.223,45.564 35.373,45.414 35.373,45.164 34.498,45.164 34.498,45.589 34.723,45.814 35.223,45.814
  region net GND: 47.098,44.964 47.293,44.769 47.293,43.914 46.403,43.914 46.403,44.769 46.598,44.964
  region net GND: 48.373,44.964 48.568,44.769 48.568,43.914 47.678,43.914 47.678,44.769 47.873,44.964
  region net GND: 49.648,44.964 49.843,44.769 49.843,43.914 48.953,43.914 48.953,44.769 49.148,44.964
  region net GND: 50.923,44.964 51.118,44.769 51.118,43.914 50.228,43.914 50.228,44.769 50.423,44.964
  region net GND: 30.848,44.012 31.043,43.817 31.043,43.362 30.153,43.362 30.153,43.817 30.348,44.012
  region net GND: 32.148,44.012 32.343,43.817 32.343,43.362 31.453,43.362 31.453,43.817 31.648,44.012
  region net GND: 33.448,44.012 33.643,43.817 33.643,43.362 32.753,43.362 32.753,43.817 32.948,44.012
  region net GND: 24.498,35.439 24.693,35.634 25.473,35.634 25.473,34.744 24.693,34.744 24.498,34.939
  region net GND: 24.498,34.139 24.693,34.334 25.473,34.334 25.473,33.444 24.693,33.444 24.498,33.639
  region net GND: 24.498,32.839 24.693,33.034 25.473,33.034 25.473,32.144 24.693,32.144 24.498,32.339
  region net VDD_DDR: 27.193,35.754 27.193,35.87 27.546,36.223 27.546,37.354 27.193,37.354 26.553,37.354 26.196,37.354 26.196,36.158 26.553,35.801 26.553,35.377 27.193,35.377
  region net GND: 35.498,39.462 35.695,39.659 36.148,39.659 36.148,38.769 35.691,38.769 35.498,38.962
  region net 5V_STLK: 38.073,39.989 38.168,39.894 38.168,39.589 37.528,39.589 37.528,39.944 37.573,39.989 37.573,40.239 38.073,40.239
  region net GND: 32.823,31.091 32.628,31.286 32.628,31.741 33.518,31.741 33.518,31.286 33.323,31.091
  region net 5V_STLK: 34.148,33.759 34.148,33.539 33.728,33.119 32.048,33.119 32.048,33.664 32.298,33.664 32.393,33.759
  region net GND: 30.973,30.889 31.018,30.844 31.578,30.844 31.623,30.889 31.623,31.484 31.318,31.484 31.223,31.389 30.973,31.389
  region net GND: 24.523,30.937 24.373,30.787 24.373,30.537 25.198,30.537 25.198,31.012 25.023,31.187 24.523,31.187
  region net GND: 24.523,30.937 24.673,30.787 24.673,30.537 23.798,30.537 23.798,30.962 24.023,31.187 24.523,31.187
  region net GND: 26.323,30.937 26.173,30.787 26.173,30.537 26.998,30.537 26.998,31.012 26.823,31.187 26.323,31.187
  region net GND: 26.323,30.937 26.473,30.787 26.473,30.537 25.598,30.537 25.598,30.962 25.823,31.187 26.323,31.187
  region net GND: 28.123,30.937 27.973,30.787 27.973,30.537 28.798,30.537 28.798,31.012 28.623,31.187 28.123,31.187
  region net GND: 28.123,30.937 28.273,30.787 28.273,30.537 27.398,30.537 27.398,30.962 27.623,31.187 28.123,31.187
  region net GND: 29.923,30.937 29.773,30.787 29.773,30.537 30.598,30.537 30.598,31.012 30.423,31.187 29.923,31.187
  region net GND: 29.923,30.937 30.073,30.787 30.073,30.537 29.198,30.537 29.198,30.962 29.423,31.187 29.923,31.187
  region net 5V_STLK: 30.973,30.087 31.623,30.087 31.623,29.444 31.318,29.444 31.223,29.539 30.973,29.539
  region net VDDIO: 52.478,28.974 52.478,28.858 52.125,28.505 52.125,27.374 52.478,27.374 53.118,27.374 53.475,27.374 53.475,28.57 53.118,28.927 53.118,29.351 52.478,29.351
  region net GND: 52.448,38.964 52.643,38.769 52.643,37.914 51.753,37.914 51.753,38.769 51.948,38.964
  region net GND: 51.148,38.964 51.343,38.769 51.343,37.914 50.453,37.914 50.453,38.769 50.648,38.964
  region net GND: 49.848,38.964 50.043,38.769 50.043,37.914 49.153,37.914 49.153,38.769 49.348,38.964
  region net GND: 48.548,38.964 48.743,38.769 48.743,37.914 47.853,37.914 47.853,38.769 48.048,38.964
  region net GND: 47.198,36.464 47.003,36.269 46.148,36.269 46.148,37.159 47.003,37.159 47.198,36.964
  region net GND: 35.173,41.512 35.368,41.317 35.368,40.862 34.478,40.862 34.478,41.317 34.673,41.512
  region net GND: 47.223,38.114 47.028,37.919 46.173,37.919 46.173,38.809 47.028,38.809 47.223,38.614
  region net GND: 47.4,32.514 47.205,32.319 46.898,32.319 46.898,33.209 47.373,33.209 47.568,33.014 47.568,32.514
  region net GND: 53.498,31.437 53.498,32.79 52.098,32.79 52.098,31.437
  region net GND: 51.698,31.437 51.698,32.79 50.298,32.79 50.298,31.437
  region net GND: 49.898,31.437 49.898,32.79 48.498,32.79 48.498,31.437
  pour cut-out: 73.519,39.825 64.7,39.825 64.7,27.95 73.466,27.95 73.455,25.398 93.508,25.398 93.508,44.648 73.54,44.648
Signal Layer 1:
  text "2" at 121.175,16.8 h1.2 r90
Signal Layer 2:
  pour cut-out: 72.125,39.275 72.125,43.075 78.675,49.625 85.125,49.625 85.65,49.1 85.65,48 84.675,47.025 83.075,47.025 75.351,39.301
  pour cut-out: 73.85,41.625 90.025,41.625 90.2,41.45 90.2,24.65 73.825,24.65 73.775,24.6
  text "3" at 121.175,18.05 h1.2 r90
Signal Layer 3:
  text "4" at 121.175,19.3 h1.2 r90
Signal Layer 4:
  text "5" at 121.175,20.55 h1.2 r90
Bottom Layer:
  region: -84.444,-0.677
  region: -84.444,-0.677
  pour cut-out: 76.626,38.217 91.701,38.217 91.701,22.142 76.626,22.142
  text "6" at 121.175,21.8 h1.2 r90
Multi-Layer:
  pour cut-out: 119.8,15.425 121.55,15.425 121.55,23.05 119.8,23.05

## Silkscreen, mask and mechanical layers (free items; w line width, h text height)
Top Overlay:
  text "J" at 52.575,79.925 h20
Bottom Overlay:
  lines w0.1: 55.225,72.525 55.225,47.925 76.7,47.925 76.7,72.528 55.225,72.528 ; 69.675,44.8 70.025,44.45 ; 70.025,47.85 70.025,44.45 ; 70.375,44.8 70.025,44.45
  text "J" at 31.1,87.65 h15
Top Paste:
  text ".Layer_Name" at 27.423,-26.172 h3
  text ".GTP" at 69.118,-26.172 h3
Bottom Paste:
  text ".GBP" at 57.907,-26.196 h3
  text ".Layer_Name" at 99.221,-26.196 h3
Top Solder:
  region: 119.8,15.425 121.55,15.425 121.55,23.05 119.8,23.05
  text ".Layer_Name" at 27.423,-26.172 h3
  text ".GTS" at 69.118,-26.172 h3
Bottom Solder:
  region: 119.8,15.425 121.55,15.425 121.55,23.05 119.8,23.05
  text ".GBS" at 57.907,-26.196 h3
  text ".Layer_Name" at 99.221,-26.196 h3
M1-Board Shape:
  the board outline again, w0.1
M14-Top Assembly:
  text ".Layer_Name" at 27.423,-26.172 h3
  text ".GM14" at 69.118,-26.172 h3
M15-Bottom Assembly:
  text ".GM15" at 57.907,-26.196 h3
  text ".Layer_Name" at 99.221,-26.196 h3
Drill Drawing:
  drawing of 407 lines, arcs and shapes, not listed
  text "MINIMUN PARAMETERS" at 150.3,143.65 h3
  text "PCB SPECIFICATIONS :" at -1.425,142.95 h3
  text "A.   MATERIAL :" at -1.425,138.95 h3
  text "FR-4" at 37.075,138.95 h3
  text "TG-170" at 53.575,138.95 h3
  text "X  TG-150" at 71.825,138.95 h3
  text "TG-140" at 87.825,138.95 h3
  text "DEFAULT" at 150.3,138.15 h3
  text "B.   MATERIAL FAMILY :" at -1.425,135.95 h3
  text "N/A" at 37.075,135.95 h3
  text "C.   SOLDERMASK COLOR :" at -1.425,132.95 h3
  text "GREEN" at 37.075,132.95 h3
  text "X  BLUE" at 53.575,132.95 h3
  text "RED" at 71.825,132.95 h3
  text "BLACK" at 87.825,132.95 h3
  text "TRACKS : 0.100mm           / GAPS : 0.100mm" at 150.3,132.4 h3
  text "D.   SILKSCREEN COLOR :" at -1.425,129.95 h3
  text "X  WHITE" at 37.075,129.95 h3
  text "YELLOW" at 53.575,129.95 h3
  text "BLACK" at 71.825,129.95 h3
  text "E.   SURFACE FINISH :" at -1.425,126.95 h3
  text "X  ENIG" at 37.075,126.95 h3
  text "IMMERSION SILVER" at 53.575,126.95 h3
  text "IMMERSION TIN" at 87.825,126.95 h3
  text "UNDER MPU" at 150.3,125.9 h3
  text "HASL" at 37.075,123.95 h3
  text "HASL (PB-FREE)" at 53.575,123.95 h3
  text "GOLDEN FINGER" at 87.825,123.95 h3
  text "F.   IMPEDANCE CONTROL :" at -1.425,120.95 h3
  text "NO" at 37.075,120.95 h3
  text "X  YES  (SEE IMPEDANCE TABLE FOR DETAIL INFORMATION)" at 53.575,120.95 h3
  text "TRACKS : 0.075mm           / GAPS : 0.082mm" at 150.3,120.15 h3
  text "G.   THROUGH VIA :" at -1.425,117.95 h3
  text "PLUG THE VIAS WHICH ARE COVERED WITH SOLDERMASK ONE OR TWO SIDE." at 37.075,117.95 h3
  text "PLUG MATERIAL :" at 37.075,114.95 h3
  text "X  SOLDERMASK" at 62.575,114.95 h3
  text "NON-CONDUCTIVE EPOXY." at 87.825,114.95 h3
  text "UNDER DDR" at 150.3,113.9 h3
  text "H.   STACK-UP :" at -1.425,111.95 h3
  text "SEE LAYER STACK-UP SEQUENCE FOR OVERALL THICKNESS." at 37.075,111.95 h3
  text "TRACKS : 0.090mm           / GAPS : 0.090mm" at 150.3,108.15 h3
  text "Layer" at 135.6,101.625 h2
  text "Name" at 143.974,101.625 h2
  text "Material" at 160.171,101.625 h2
  text "Thickness" at 174.725,101.625 h2
  text "Constant" at 186.68,101.625 h2
  text "Board Layer Stack" at 197.744,101.625 h2
  text "Top Overlay" at 143.974,97.625 h2
  text "Top Solder" at 143.974,93.625 h2
  text "Solder Resist" at 160.171,93.625 h2
  text "0.025mm" at 174.725,93.625 h2
  text "3.5" at 186.68,93.625 h2
  text "1" at 135.6,89.625 h2
  text "Top Layer" at 143.974,89.625 h2
  text "0.046mm" at 174.725,89.625 h2
  text "Dielectric 1" at 143.974,85.625 h2
  text "0.071mm" at 174.725,85.625 h2
  text "4.21" at 186.68,85.625 h2
  text "2" at 135.598,81.625 h2
  text "Signal Layer 1" at 143.974,81.625 h2
  text "0.035mm" at 174.725,81.625 h2
  text "Dielectric 2" at 143.974,77.625 h2
  text "0.094mm" at 174.725,77.625 h2
  text "4.09" at 186.68,77.625 h2
  text "3" at 135.6,73.625 h2
  text "Signal Layer 2" at 143.974,73.625 h2
  text "0.023mm" at 174.725,73.625 h2
  text "Dielectric 3" at 143.974,69.625 h2
  text "0.865mm" at 174.725,69.625 h2
  text "4.68" at 186.68,69.625 h2
  text "4" at 135.6,65.625 h2
  text "Signal Layer 3" at 143.974,65.625 h2
  text "0.023mm" at 174.725,65.625 h2
  text "Dielectric 4" at 143.974,61.625 h2
  text "0.094mm" at 174.725,61.625 h2
  text "4.09" at 186.68,61.625 h2
  text "5" at 135.6,57.625 h2
  text "Signal Layer 4" at 143.974,57.625 h2
  text "0.035mm" at 174.725,57.625 h2
  text "Dielectric5" at 143.974,53.625 h2
  text "0.071mm" at 174.725,53.625 h2
  text "4.21" at 186.68,53.625 h2
  text "6" at 135.6,49.625 h2
  text "Bottom Layer" at 143.974,49.625 h2
  text "0.046mm" at 174.725,49.625 h2
  text "Bottom Solder" at 143.974,45.625 h2
  text "Solder Resist" at 160.171,45.625 h2
  text "0.025mm" at 174.725,45.625 h2
  text "3.5" at 186.68,45.625 h2
  text "Bottom Overlay" at 143.974,41.625 h2
  text "Symbol" at 136.02,-15.1 h2.4
  text "Count" at 145.419,-15.1 h2.4
  text "Hole Size" at 155.174,-15.1 h2.4
  text "Plated" at 173.451,-15.1 h2.4
  text "Hole Type" at 181.702,-15.1 h2.4
  text "Drill Layer Pair" at 193.714,-15.1 h2.4
  text "Via/Pad" at 216.494,-15.1 h2.4
  text "Pad Shape" at 226.337,-15.1 h2.4
  text "Template" at 239.194,-15.1 h2.4
  text "Hole Tolerance (+)" at 270.377,-15.1 h2.4
  text "Hole Tolerance (-)" at 290.456,-15.1 h2.4
  text "2" at 145.419,-19.243 h2
  text "0.500mm (19.69mil)" at 155.174,-19.243 h2
  text "PTH" at 173.451,-19.243 h2
  text "Round" at 181.702,-19.243 h2
  text "Top Layer - Bottom Layer" at 193.714,-19.243 h2
  text "Pad" at 216.494,-19.243 h2
  text "Rounded" at 226.337,-19.243 h2
  text "r100_130h50r100m105_135(Tol5-5)" at 239.194,-19.243 h2
  text "0.050mm (1.97mil)" at 270.377,-19.243 h2
  text "0.050mm (1.97mil)" at 290.456,-19.243 h2
  text "55" at 145.419,-23.386 h2
  text "0.350mm (13.78mil)" at 155.174,-23.386 h2
  text "PTH" at 173.451,-23.386 h2
  text "Round" at 181.702,-23.386 h2
  text "Top Layer - Bottom Layer" at 193.714,-23.386 h2
  text "Via" at 216.494,-23.386 h2
  text "Rounded" at 226.337,-23.386 h2
  text "v55h35m40mx40" at 239.194,-23.386 h2
  text "394" at 145.419,-27.529 h2
  text "0.200mm (7.87mil)" at 155.174,-27.529 h2
  text "PTH" at 173.451,-27.529 h2
  text "Round" at 181.702,-27.529 h2
  text "(Mixed)" at 193.714,-27.529 h2
  text "Via" at 216.494,-27.529 h2
  text "Rounded" at 226.337,-27.529 h2
  text "(Mixed)" at 239.194,-27.529 h2
  text "490" at 145.419,-31.672 h2
  text "0.100mm (3.94mil)" at 155.174,-31.672 h2
  text "PTH" at 173.451,-31.672 h2
  text "Round" at 181.702,-31.672 h2
  text "(Mixed)" at 193.714,-31.672 h2
  text "Via" at 216.494,-31.672 h2
  text "Rounded" at 226.337,-31.672 h2
  text "v26h10" at 239.194,-31.672 h2
  text "941 Total" at 145.419,-35.815 h2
